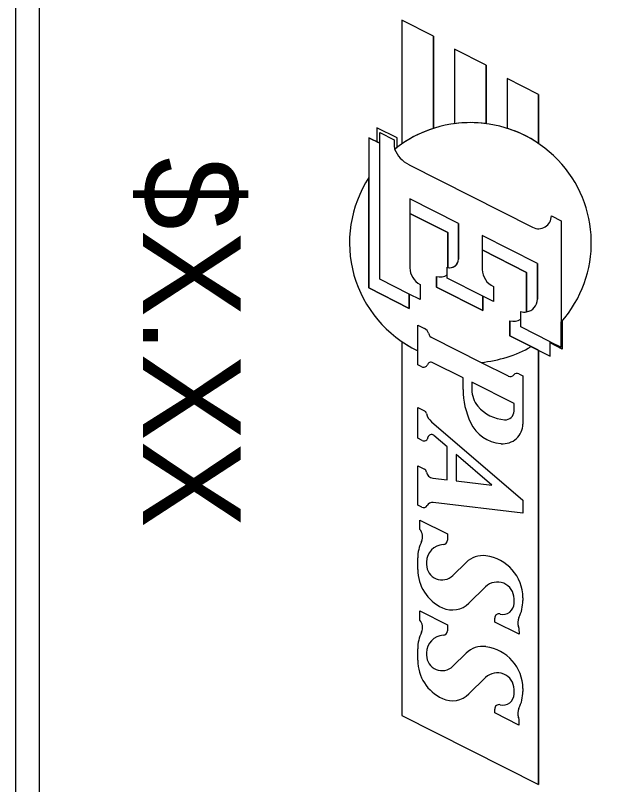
# Model space of a CAD drawing. Extents: x 46672 to 47298, y 5424 to 5742.
# Drawn here: x 47141.98 to 47157.28, y 5575.78 to 5595.82 of the extents above; entities that cross this region are included whole.
import ezdxf

# ---------------------------------------------------------------- set-up
doc = ezdxf.new("R2010")
doc.units = 0
doc.layers.add('SignPanel', color=7, linetype='Continuous')

msp = doc.modelspace()

# ---------------------------------------------------------------- linework, layer by layer
at = {"layer": 'SignPanel'}
for p, q in [((47141.977, 5598.386), (47141.977, 5557.433)), ((47142.607, 5557.433), (47142.607, 5598.386)), ((47152.872, 5595.286), (47152.05, 5595.703)), ((47152.05, 5595.703), (47152.05, 5592.48)), ((47152.872, 5595.286), (47152.05, 5595.703)), ((47152.05, 5595.703), (47152.05, 5592.48)), ((47152.872, 5595.286), (47152.872, 5592.881)), ((47152.872, 5592.881), (47152.872, 5595.286)), ((47154.242, 5594.524), (47153.42, 5594.94)), ((47153.42, 5594.94), (47153.42, 5593.003)), ((47154.242, 5594.524), (47153.42, 5594.94)), ((47153.42, 5594.94), (47153.42, 5593.003)), ((47154.242, 5594.524), (47154.242, 5593.003)), ((47154.242, 5593.003), (47154.242, 5594.524)), ((47155.611, 5593.761), (47154.79, 5594.177)), ((47154.79, 5594.177), (47154.79, 5592.882)), ((47155.611, 5593.761), (47154.79, 5594.177)), ((47154.79, 5594.177), (47154.79, 5592.882)), ((47155.611, 5593.761), (47155.611, 5592.484)), ((47155.611, 5592.484), (47155.611, 5593.761)), ((47151.471, 5588.955), (47151.471, 5592.776)), ((47151.189, 5592.633), (47151.471, 5592.491)), ((47151.471, 5592.491), (47151.189, 5592.633)), ((47151.189, 5592.633), (47151.189, 5588.722)), ((47151.471, 5588.955), (47151.471, 5592.491)), ((47151.189, 5588.722), (47151.189, 5591.602)), ((47153.524, 5590.402), (47152.258, 5591.042)), ((47153.524, 5590.402), (47152.258, 5591.042)), ((47152.258, 5591.042), (47152.258, 5590.666)), ((47152.258, 5590.666), (47153.243, 5590.168)), ((47152.258, 5590.666), (47153.243, 5590.168)), ((47153.243, 5590.168), (47152.258, 5590.666)), ((47152.258, 5590.666), (47152.258, 5589.248)), ((47153.524, 5590.402), (47153.524, 5589.473)), ((47153.524, 5589.473), (47153.524, 5590.402)), ((47153.243, 5590.168), (47153.243, 5589.256)), ((47153.243, 5590.168), (47153.243, 5589.256)), ((47153.243, 5589.256), (47153.243, 5590.168)), ((47155.578, 5589.363), (47154.143, 5590.089)), ((47155.578, 5589.363), (47154.143, 5590.089)), ((47154.143, 5590.089), (47154.143, 5589.713)), ((47154.143, 5589.713), (47155.296, 5589.129)), ((47154.143, 5589.713), (47155.296, 5589.129)), ((47155.296, 5589.129), (47154.143, 5589.713)), ((47154.143, 5589.713), (47154.143, 5589.205)), ((47153.232, 5589.063), (47153.232, 5589.26)), ((47155.578, 5589.363), (47155.578, 5588.43)), ((47155.578, 5588.43), (47155.578, 5589.363)), ((47153.232, 5588.977), (47153.232, 5589.063)), ((47155.296, 5589.129), (47155.296, 5588.1)), ((47155.296, 5589.129), (47155.296, 5588.1)), ((47155.296, 5588.1), (47155.296, 5589.129)), ((47152.242, 5588.565), (47151.471, 5588.955)), ((47152.951, 5589.022), (47152.951, 5588.743)), ((47152.951, 5588.743), (47152.951, 5589.022)), ((47152.951, 5588.743), (47152.951, 5589.022)), ((47154.154, 5588.51), (47153.232, 5588.977)), ((47151.189, 5588.722), (47152.242, 5588.189)), ((47151.189, 5588.722), (47152.242, 5588.189)), ((47152.242, 5588.189), (47151.189, 5588.722)), ((47152.951, 5588.743), (47154.154, 5588.134)), ((47154.154, 5588.134), (47152.951, 5588.743)), ((47154.154, 5588.134), (47152.951, 5588.743)), ((47152.242, 5588.189), (47152.242, 5588.565)), ((47152.242, 5588.189), (47152.242, 5588.565)), ((47152.242, 5588.565), (47152.242, 5588.189)), ((47154.154, 5588.134), (47154.154, 5588.51)), ((47154.154, 5588.51), (47154.154, 5588.134)), ((47154.154, 5588.51), (47154.154, 5588.134)), ((47155.144, 5587.91), (47155.144, 5588.109)), ((47154.863, 5587.869), (47154.863, 5587.478)), ((47154.863, 5587.869), (47154.863, 5587.478)), ((47154.863, 5587.478), (47154.863, 5587.869)), ((47155.144, 5587.711), (47155.144, 5587.91)), ((47152.461, 5587.085), (47152.461, 5587.753)), ((47152.461, 5587.753), (47152.64, 5587.663)), ((47155.915, 5587.321), (47155.144, 5587.711)), ((47154.863, 5587.478), (47155.915, 5586.945)), ((47155.418, 5587.197), (47154.863, 5587.478)), ((47152.05, 5587.322), (47152.05, 5577.586)), ((47152.05, 5587.322), (47152.05, 5577.586)), ((47152.845, 5587.42), (47154.111, 5586.784)), ((47155.915, 5586.945), (47155.915, 5587.321)), ((47155.611, 5587.099), (47155.611, 5575.784)), ((47155.611, 5575.784), (47155.611, 5587.099)), ((47152.569, 5586.67), (47152.461, 5586.724)), ((47153.641, 5586.38), (47152.855, 5586.775)), ((47154.111, 5586.784), (47154.111, 5586.784)), ((47154.111, 5586.784), (47154.817, 5586.429)), ((47155.092, 5586.487), (47155.201, 5586.433)), ((47155.201, 5586.433), (47155.201, 5585.178)), ((47153.641, 5586.077), (47153.641, 5586.38)), ((47154.97, 5585.712), (47153.871, 5586.264)), ((47153.871, 5586.264), (47153.871, 5586.077)), ((47154.97, 5585.517), (47154.97, 5585.712)), ((47152.461, 5584.806), (47152.461, 5585.606)), ((47152.461, 5585.606), (47152.635, 5585.519)), ((47152.817, 5585.238), (47155.201, 5583.196)), ((47153.232, 5584.581), (47152.879, 5584.883)), ((47152.578, 5584.747), (47152.461, 5584.806)), ((47154.635, 5584.665), (47154.623, 5584.666)), ((47153.232, 5583.724), (47153.232, 5584.581)), ((47154.396, 5583.583), (47153.462, 5584.383)), ((47153.462, 5584.383), (47153.462, 5583.696)), ((47152.461, 5583.062), (47152.461, 5584.091)), ((47152.461, 5584.091), (47152.635, 5584.004)), ((47152.851, 5583.77), (47153.232, 5583.724)), ((47153.462, 5583.696), (47154.396, 5583.583)), ((47152.566, 5583.01), (47152.461, 5583.062)), ((47155.201, 5582.852), (47152.864, 5583.135)), ((47155.201, 5583.196), (47155.201, 5582.852)), ((47152.512, 5582.434), (47152.512, 5582.677)), ((47152.512, 5582.677), (47153.235, 5582.314)), ((47153.235, 5582.314), (47153.235, 5582.153)), ((47152.461, 5581.387), (47152.461, 5581.688)), ((47152.691, 5581.582), (47152.691, 5581.517)), ((47153.378, 5581.233), (47153.722, 5581.572)), ((47154.225, 5580.936), (47153.793, 5580.51)), ((47154.97, 5580.505), (47154.97, 5580.627)), ((47155.201, 5580.652), (47155.201, 5580.576)), ((47152.512, 5580.069), (47152.512, 5580.312)), ((47152.512, 5580.312), (47153.235, 5579.948)), ((47154.466, 5580.018), (47154.466, 5580.118)), ((47153.235, 5579.948), (47153.235, 5579.788)), ((47155.1, 5579.7), (47154.466, 5580.018)), ((47155.099, 5579.85), (47155.1, 5579.7)), ((47152.461, 5579.023), (47152.461, 5579.324)), ((47152.691, 5579.217), (47152.691, 5579.152)), ((47153.378, 5578.868), (47153.722, 5579.207)), ((47154.225, 5578.571), (47153.793, 5578.145)), ((47154.97, 5578.141), (47154.97, 5578.263)), ((47155.201, 5578.287), (47155.201, 5578.211)), ((47154.466, 5577.653), (47154.466, 5577.753)), ((47155.099, 5577.335), (47154.466, 5577.653)), ((47152.05, 5577.586), (47155.611, 5575.784)), ((47152.05, 5577.586), (47155.611, 5575.784)), ((47155.099, 5577.486), (47155.099, 5577.335))]:
    msp.add_line(p, q, dxfattribs=at)
for points in [[(47151.924, 5592.387), (47151.924, 5592.63), (47151.396, 5592.897), (47151.396, 5592.529), (47151.471, 5592.491), (47151.471, 5592.776), (47151.849, 5592.585), (47151.849, 5592.428), (47151.856, 5592.337)], [(47156.225, 5587.865), (47156.225, 5587.132), (47155.915, 5587.289), (47155.915, 5587.321), (47156.196, 5587.179), (47156.196, 5587.831)]]:
    msp.add_lwpolyline(points, close=True, dxfattribs=at)
for points in [[(47152.872, 5592.88), (47152.872, 5592.881)], [(47153.42, 5593.003), (47153.42, 5593.003)], [(47152.225, 5591.937), (47152.239, 5591.93), (47155.455, 5590.303)], [(47155.946, 5590.602), (47156.196, 5590.475), (47156.196, 5587.831)], [(47153.232, 5589.26), (47153.232, 5589.26), (47153.243, 5589.256)], [(47152.951, 5589.022), (47152.951, 5589.022)], [(47152.523, 5588.814), (47152.523, 5588.423), (47152.242, 5588.565)], [(47154.435, 5588.76), (47154.435, 5588.368), (47154.154, 5588.51)], [(47154.863, 5587.869), (47154.863, 5587.869)], [(47155.144, 5587.91), (47155.144, 5587.91)], [(47152.05, 5587.322), (47152.05, 5587.322)], [(47152.461, 5586.724), (47152.461, 5587.085), (47152.461, 5587.085)], [(47155.418, 5587.197), (47155.418, 5587.197)], [(47155.611, 5587.099), (47155.611, 5587.099), (47155.418, 5587.197)], [(47155.418, 5587.197), (47155.418, 5587.197)], [(47154.111, 5586.784), (47154.111, 5586.784)]]:
    msp.add_lwpolyline(points, dxfattribs=at)
for centre, radius, start, end in [((47152.608, 5592.661), 0.819, 203.3441, 242.1501), ((47155.608, 5590.603), 0.337, 242.981, 359.777), ((47152.747, 5589.248), 0.489, 180.0902, 242.7431), ((47154.629, 5589.206), 0.486, 180.0941, 246.5148), ((47155.24, 5588.431), 0.336, 253.3916, 279.6757)]:
    msp.add_arc(centre, radius, start, end, dxfattribs=at)
for centre, major_axis, ratio, start_param, end_param in [((47153.834, 5589.901), (3.15, 0), 0.993175, 5.560451, 8.532552), ((47153.834, 5589.901), (3.15, 0), 0.993175, 5.560451, 8.532552), ((47153.834, 5589.901), (3.15, 0), 0.993175, 1.880935, 2.172526), ((47153.834, 5589.901), (3.15, 0), 0.993175, 1.440864, 1.702425), ((47153.834, 5589.901), (3.15, 0), 0.993175, 0.971144, 1.262423), ((47153.834, 5589.901), (3.15, 0), 0.993175, 2.566764, 4.26163), ((47153.834, 5589.901), (3.15, 0), 0.993175, 2.566863, 4.261593), ((47153.299, 5589.473), (0.225, 0), 0.993175, 4.409792, 6.283185), ((47153.299, 5589.473), (0.225, 0), 0.993175, 4.459709, 6.283185), ((47153.299, 5589.473), (0.225, 0), 0.993175, 4.459709, 4.459886), ((47153.047, 5589.343), (-0.338, 0), 0.993175, 1.282138, 2.151565), ((47153.047, 5589.343), (-0.338, 0), 0.993175, 1.282138, 2.151565), ((47153.047, 5589.343), (-0.338, 0), 0.993175, 1.282138, 2.151565), ((47155.24, 5588.43), (-0.338, 0), 0.993175, 1.738244, 3.141593), ((47154.959, 5588.19), (-0.338, 0), 0.993175, 1.282138, 2.151565), ((47154.959, 5588.19), (-0.338, 0), 0.993175, 1.282138, 2.151565), ((47154.959, 5588.19), (-0.338, 0), 0.993175, 1.282138, 2.151565), ((47152.548, 5587.485), (-0.203, 0), 0.98584, 3.428379, 4.240701), ((47152.937, 5587.598), (-0.203, 0), 0.98584, 0.286787, 1.099486), ((47153.834, 5589.901), (3.15, 0), 0.993175, 4.110614, 4.261593), ((47153.834, 5589.901), (3.15, 0), 0.993175, 4.800546, 5.239396), ((47153.834, 5589.901), (3.15, 0), 0.993175, 4.800546, 5.239396), ((47153.834, 5589.901), (3.15, 0), 0.993175, 4.800546, 5.239396), ((47152.616, 5586.761), (-0.104, 0), 0.993175, 1.102055, 2.750085), ((47152.808, 5586.683), (-0.104, 0), 0.993175, 4.24413, 5.891677), ((47154.872, 5586.536), (-0.122, 0), 0.98584, 1.099604, 2.46371), ((47155.046, 5586.398), (-0.101, 0), 0.98584, 4.240773, 5.605302), ((47155.656, 5586.077), (-2.014, 0), 0.993175, 0, 0.446437), ((47154.562, 5586.077), (-0.691, 0), 0.993175, 0, 0.687568), ((47154.784, 5586.259), (0.978, 0), 0.993175, 3.82916, 4.653281), ((47152.589, 5585.43), (-0.101, 0), 0.98584, 3.363532, 4.241567), ((47153.084, 5585.54), (-0.406, 0), 0.98584, 0.22194, 0.855152), ((47154.74, 5585.517), (0.23, 0), 0.993175, 4.653281, 6.283185), ((47154.721, 5585.633), (0.978, 0), 0.993175, 3.58803, 4.61224), ((47154.683, 5585.178), (0.518, 0), 0.993175, 4.619204, 6.283185), ((47152.819, 5584.814), (-0.0921, 0), 0.993175, 4.000286, 6.153012), ((47152.625, 5584.839), (-0.104, 0), 0.993175, 1.102454, 3.011419), ((47152.588, 5583.912), (0.104, 0), 0.993175, 0.138764, 1.102914), ((47152.873, 5583.951), (0.184, 0), 0.993175, 3.280357, 4.591647), ((47152.612, 5583.102), (-0.104, 0), 0.993175, 1.104515, 2.643546), ((47152.845, 5582.976), (-0.161, 0), 0.993175, 4.59125, 5.785138), ((47152.305, 5582.242), (-0.284, 0), 0.98584, 2.69443, 3.895387), ((47153.476, 5581.688), (-1.015, 0), 0.98584, 5.836023, 6.283185), ((47153.152, 5581.582), (0.46, 0), 0.993175, 1.626024, 3.141593), ((47153.12, 5582.153), (0.115, 0), 0.993175, 4.767617, 6.283185), ((47154.153, 5581.148), (0.609, 0), 0.98584, 1.436562, 2.356194), ((47154.085, 5580.652), (1.116, 0), 0.98584, 0, 1.436562), ((47153.094, 5581.517), (0.403, 0), 0.993175, 3.141593, 5.49392), ((47153.577, 5581.387), (-1.116, 0), 0.98584, 0, 1.133591), ((47154.533, 5580.627), (0.437, 0), 0.993175, 0, 2.352496), ((47153.363, 5580.934), (-0.609, 0), 0.98584, 1.133591, 2.356194), ((47154.683, 5580.505), (-0.288, 0), 0.993175, 1.31664, 3.141593), ((47154.186, 5580.576), (1.015, 0), 0.98584, 5.830963, 6.283185), ((47154.581, 5580.118), (-0.115, 0), 0.993175, 4.458233, 6.283185), ((47152.305, 5579.877), (-0.284, 0), 0.98584, 2.69443, 3.895387), ((47155.373, 5580.008), (0.304, 0), 0.98584, 2.68937, 3.526171), ((47154.978, 5579.85), (0.122, 0), 0.98584, 0, 0.384579), ((47153.476, 5579.324), (-1.015, 0), 0.98584, 5.836023, 6.283185), ((47153.152, 5579.217), (0.46, 0), 0.993175, 1.626024, 3.141593), ((47153.12, 5579.788), (0.115, 0), 0.993175, 4.767617, 6.283185), ((47154.153, 5578.783), (0.609, 0), 0.98584, 1.436562, 2.356194), ((47154.085, 5578.287), (1.116, 0), 0.98584, 0, 1.436562), ((47153.577, 5579.023), (-1.116, 0), 0.98584, 0, 1.133591), ((47153.094, 5579.152), (0.403, 0), 0.993175, 3.141593, 5.49392), ((47154.533, 5578.263), (0.437, 0), 0.993175, 0, 2.352496), ((47153.363, 5578.57), (-0.609, 0), 0.98584, 1.133591, 2.356194), ((47154.683, 5578.141), (-0.288, 0), 0.993175, 1.31664, 3.141593), ((47154.186, 5578.211), (1.015, 0), 0.98584, 5.830963, 6.283185), ((47154.581, 5577.753), (-0.115, 0), 0.993175, 4.458233, 6.283185), ((47155.373, 5577.643), (0.304, 0), 0.98584, 2.68937, 3.526171), ((47154.978, 5577.486), (0.122, 0), 0.98584, 0, 0.384579)]:
    msp.add_ellipse(centre, major_axis=major_axis, ratio=ratio, start_param=start_param, end_param=end_param, dxfattribs=at)

# ---------------------------------------------------------------- texts
msp.add_text('$X.XX', height=2.5485, rotation=270, dxfattribs=at).set_placement((47145.301, 5592.132))

doc.saveas('drawing.dxf')
